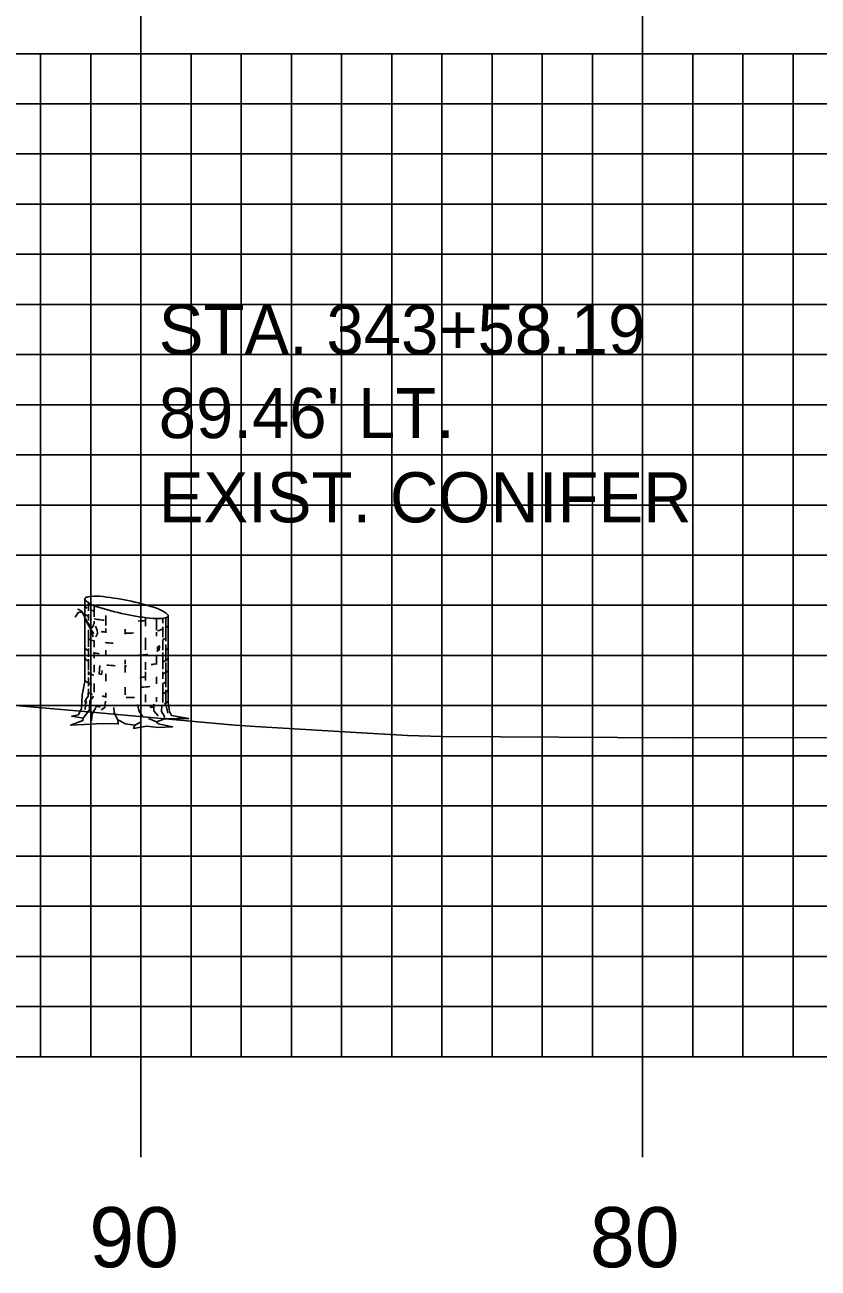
# Model space of a CAD drawing. Extents: x 1825147 to 1825490, y 442591 to 442811.
# Drawn here: x 1825220.05 to 1825235.86, y 442764.45 to 442789.24 of the extents above; entities that cross this region are included whole.
import ezdxf

# ---------------------------------------------------------------- set-up
doc = ezdxf.new("R2010")
doc.units = 0
for name, color, linetype in [('D_Text_Monospaced', 7, 'Continuous'), ('H_V ANNOTATION', 7, 'Continuous'), ('M_Trees_Conifer_Pay', 7, 'Continuous'), ('MAJOR', 7, 'Continuous'), ('MINOR', 7, 'Continuous'), ('S_Roadway_Centerline', 7, 'Continuous')]:
    doc.layers.add(name, color=color, linetype=linetype)

msp = doc.modelspace()

# ---------------------------------------------------------------- linework, layer by layer
at = {"layer": 'M_Trees_Conifer_Pay'}
for p, q in [((1825221.242, 442776.145), (1825221.242, 442777.792)), ((1825221.313, 442777.719), (1825221.313, 442777.557)), ((1825221.313, 442777.489), (1825221.313, 442777.361)), ((1825221.431, 442777.658), (1825221.431, 442777.435)), ((1825221.431, 442777.347), (1825221.431, 442777.299)), ((1825221.659, 442777.462), (1825221.659, 442777.263)), ((1825222.455, 442777.42), (1825222.455, 442777.252)), ((1825222.675, 442777.4), (1825222.675, 442777.168)), ((1825222.8, 442777.408), (1825222.8, 442777.31)), ((1825222.8, 442777.236), (1825222.8, 442777.032)), ((1825222.859, 442777.419), (1825222.859, 442776.948)), ((1825222.906, 442775.734), (1825222.906, 442777.456)), ((1825221.313, 442777.174), (1825221.313, 442776.838)), ((1825221.374, 442777.164), (1825221.425, 442777.104)), ((1825221.659, 442777.205), (1825221.659, 442777.116)), ((1825222.05, 442777.189), (1825222.05, 442777.093)), ((1825222.455, 442777.015), (1825222.455, 442776.778)), ((1825222.675, 442777.127), (1825222.675, 442777.053)), ((1825221.313, 442776.801), (1825221.313, 442776.639)), ((1825221.431, 442776.964), (1825221.431, 442776.832)), ((1825221.659, 442776.769), (1825221.659, 442776.664)), ((1825222.8, 442776.974), (1825222.8, 442776.774)), ((1825222.859, 442776.883), (1825222.859, 442776.575)), ((1825221.313, 442776.591), (1825221.313, 442776.375)), ((1825221.431, 442776.721), (1825221.431, 442776.612)), ((1825222.05, 442776.575), (1825222.05, 442776.501)), ((1825222.455, 442776.534), (1825222.455, 442776.381)), ((1825222.675, 442776.649), (1825222.675, 442776.511)), ((1825222.8, 442776.727), (1825222.8, 442776.391)), ((1825222.859, 442776.528), (1825222.859, 442776.036)), ((1825221.313, 442776.344), (1825221.313, 442776.27)), ((1825221.431, 442776.476), (1825221.431, 442776.334)), ((1825221.659, 442776.297), (1825221.659, 442776.15)), ((1825222.05, 442776.476), (1825222.05, 442776.328)), ((1825222.455, 442776.338), (1825222.455, 442776.165)), ((1825222.675, 442776.239), (1825222.675, 442776.097)), ((1825222.8, 442776.338), (1825222.8, 442776.202)), ((1825221.313, 442776.229), (1825221.313, 442776.056)), ((1825221.431, 442776.107), (1825221.431, 442775.935)), ((1825222.05, 442776.036), (1825222.05, 442775.883)), ((1825222.8, 442776.103), (1825222.8, 442775.725)), ((1825221.659, 442775.918), (1825221.659, 442775.83)), ((1825222.455, 442775.887), (1825222.455, 442775.734)), ((1825222.675, 442775.835), (1825222.675, 442775.741)), ((1825222.859, 442775.982), (1825222.859, 442775.734)), ((1825222.238, 442775.277), (1825222.364, 442775.341)), ((1825222.675, 442775.341), (1825222.512, 442775.405))]:
    msp.add_line(p, q, dxfattribs=at)
for points in [[(1825221.196, 442777.522), (1825221.12, 442777.53), (1825221.048, 442777.431)], [(1825221.425, 442777.29), (1825221.388, 442777.215), (1825221.341, 442777.272), (1825221.283, 442777.341), (1825221.191, 442777.534), (1825221.126, 442777.582), (1825221.095, 442777.588)], [(1825221.41, 442777.036), (1825221.374, 442777.164), (1825221.31, 442777.279), (1825221.279, 442777.347), (1825221.21, 442777.493)], [(1825221.458, 442777.252), (1825221.489, 442777.168), (1825221.493, 442777.1), (1825221.462, 442777.036)], [(1825222.727, 442776.762), (1825222.733, 442776.857), (1825222.689, 442776.834), (1825222.689, 442776.74)], [(1825221.588, 442776.363), (1825221.575, 442776.286), (1825221.528, 442776.297), (1825221.54, 442776.463)], [(1825221.242, 442776.145), (1825221.191, 442775.883), (1825221.174, 442775.609), (1825221.116, 442775.484), (1825220.981, 442775.453), (1825221.211, 442775.416), (1825221.211, 442775.416), (1825221.205, 442775.368), (1825220.958, 442775.274), (1825221.232, 442775.29), (1825221.588, 442775.311), (1825221.909, 442775.3), (1825221.903, 442775.383), (1825222.051, 442775.3), (1825222.238, 442775.277), (1825222.214, 442775.21), (1825222.481, 442775.253), (1825222.702, 442775.226), (1825222.994, 442775.243), (1825222.706, 442775.3), (1825222.675, 442775.341), (1825222.838, 442775.399), (1825223.074, 442775.41), (1825223.315, 442775.41), (1825222.973, 442775.467), (1825222.932, 442775.547), (1825222.906, 442775.734)], [(1825221.316, 442776.002), (1825221.31, 442775.856), (1825221.263, 442775.788), (1825221.252, 442775.589)], [(1825221.415, 442775.856), (1825221.341, 442775.751), (1825221.336, 442775.578), (1825221.211, 442775.416)], [(1825221.652, 442775.751), (1825221.641, 442775.626), (1825221.567, 442775.582)], [(1825221.374, 442775.362), (1825221.388, 442775.5), (1825221.462, 442775.629)], [(1825221.903, 442775.383), (1825221.828, 442775.524), (1825221.819, 442775.626)], [(1825222.391, 442775.453), (1825222.323, 442775.547), (1825222.296, 442775.687)], [(1825222.617, 442775.694), (1825222.617, 442775.562), (1825222.706, 442775.463)], [(1825222.78, 442775.667), (1825222.774, 442775.551), (1825222.827, 442775.463), (1825222.838, 442775.399)], [(1825222.858, 442775.687), (1825222.879, 442775.609), (1825222.899, 442775.515)]]:
    msp.add_lwpolyline(points, dxfattribs=at)
for centre, radius, start, end in [((1825221.264, 442777.792), 0.0226, 156.5926, 168.2806), ((1825221.264, 442777.792), 0.0226, 168.2806, 179.9685), ((1825221.268, 442777.792), 0.0264, 179.9685, 190.7806), ((1825221.273, 442777.793), 0.0314, 190.7806, 203.4842), ((1825221.268, 442777.79), 0.0264, 145.7806, 156.5926), ((1825221.293, 442777.801), 0.0527, 203.4842, 213.2806), ((1825221.272, 442777.787), 0.0314, 133.077, 145.7806), ((1825221.317, 442777.817), 0.0817, 213.2806, 227.6113), ((1825221.286, 442777.772), 0.0527, 123.2806, 133.077), ((1825221.302, 442777.748), 0.0817, 108.9499, 123.2806), ((1825221.431, 442777.942), 0.251, 227.6113, 235.7806), ((1825221.357, 442777.588), 0.251, 100.7806, 108.9499), ((1825221.741, 442778.397), 0.802, 235.7806, 251.9406), ((1825221.46, 442777.047), 0.802, 84.6206, 100.7806), ((1825221.05, 442772.689), 5.179, 78.2806, 84.6206), ((1825221.05, 442772.689), 5.179, 71.9406, 78.2806), ((1825221.275, 442777.665), 0.0334, 185.7849, 196.0515), ((1825221.275, 442777.511), 0.0334, 185.7849, 196.0515), ((1825221.285, 442777.668), 0.0441, 196.0515, 210), ((1825221.285, 442777.514), 0.0441, 196.0515, 210), ((1825221.301, 442777.677), 0.0624, 210, 228.7494), ((1825221.301, 442777.523), 0.0624, 210, 228.7494), ((1825221.373, 442777.76), 0.172, 228.7494, 240), ((1825221.373, 442777.606), 0.172, 228.7494, 240), ((1825221.573, 442778.105), 0.571, 247.5868, 255.5683), ((1825223.097, 442782.559), 5.179, 251.9406, 258.2806), ((1825223.097, 442782.559), 5.179, 258.2806, 264.6206), ((1825222.407, 442776.85), 0.802, 55.7806, 71.9406), ((1825222.717, 442777.306), 0.251, 47.6113, 55.7806), ((1825222.831, 442777.431), 0.0817, 33.2806, 47.6113), ((1825222.855, 442777.447), 0.0527, 23.4842, 33.2806), ((1825221.573, 442777.951), 0.571, 240, 242.9763), ((1825221.573, 442777.951), 0.571, 255.6333, 261.8968), ((1825222.074, 442781.468), 4.124, 261.8968, 263.762), ((1825222.074, 442781.468), 4.124, 273.2669, 275.3045), ((1825222.687, 442778.201), 0.802, 264.6206, 280.7806), ((1825222.79, 442777.66), 0.251, 280.7806, 288.9499), ((1825222.576, 442777.718), 0.571, 299.6633, 300), ((1825222.775, 442777.373), 0.172, 300, 311.2506), ((1825222.845, 442777.5), 0.0817, 288.9499, 303.2806), ((1825222.847, 442777.29), 0.0624, 311.2506, 330), ((1825222.861, 442777.476), 0.0527, 303.2806, 313.077), ((1825222.875, 442777.46), 0.0314, 313.077, 325.7806), ((1825222.88, 442777.457), 0.0264, 325.7806, 336.5926), ((1825222.863, 442777.281), 0.0441, 330, 343.9485), ((1825222.874, 442777.455), 0.0314, 10.7806, 23.4842), ((1825222.883, 442777.456), 0.0226, 336.5926, 348.2806), ((1825222.879, 442777.456), 0.0264, 359.9685, 10.7806), ((1825222.883, 442777.456), 0.0226, 348.2806, 359.9685), ((1825222.874, 442777.278), 0.0334, 0, 16.0515), ((1825222.874, 442777.278), 0.0334, 343.9485, 360), ((1825221.275, 442777.067), 0.0334, 185.7849, 196.0515), ((1825221.573, 442777.507), 0.571, 242.9571, 255.5507), ((1825222.075, 442781.235), 4.124, 262.9442, 264.2151), ((1825222.075, 442781.235), 4.124, 269.6419, 270), ((1825222.075, 442781.235), 4.124, 270, 271.9249), ((1825222.576, 442777.718), 0.571, 282.0154, 293.1403), ((1825222.575, 442777.507), 0.571, 292.9413, 300), ((1825221.276, 442776.831), 0.0334, 185.7849, 196.0515), ((1825221.287, 442776.834), 0.0441, 196.0515, 210), ((1825221.302, 442776.843), 0.0624, 210, 228.7494), ((1825221.375, 442776.926), 0.172, 228.7494, 240), ((1825221.574, 442777.271), 0.571, 240, 242.8104), ((1825222.074, 442781.024), 4.124, 264.0496, 266.2948), ((1825222.576, 442777.271), 0.571, 299.6633, 300), ((1825222.775, 442776.926), 0.172, 300, 311.2506), ((1825222.847, 442776.843), 0.0624, 311.2506, 330), ((1825222.863, 442776.834), 0.0441, 330, 343.9485), ((1825222.874, 442776.831), 0.0334, 0, 16.0515), ((1825222.874, 442776.831), 0.0334, 343.9485, 360), ((1825221.276, 442776.621), 0.0334, 185.7849, 196.0515), ((1825221.287, 442776.624), 0.0441, 196.0515, 210), ((1825221.302, 442776.633), 0.0624, 210, 228.7494), ((1825221.375, 442776.716), 0.172, 228.7494, 240), ((1825221.574, 442777.061), 0.571, 240, 242.8104), ((1825221.574, 442777.271), 0.571, 253.0704, 261.8968), ((1825222.075, 442780.788), 4.124, 261.8968, 262.3875), ((1825222.075, 442780.788), 4.124, 273.3324, 275.919), ((1825222.075, 442780.578), 4.124, 276.8526, 278.1032), ((1825222.576, 442777.061), 0.571, 278.1032, 280.7293), ((1825222.576, 442777.061), 0.571, 293.1403, 300), ((1825222.775, 442776.716), 0.172, 300, 311.2506), ((1825222.847, 442776.633), 0.0624, 311.2506, 330), ((1825222.863, 442776.624), 0.0441, 330, 343.9485), ((1825222.874, 442776.621), 0.0334, 0, 16.0515), ((1825222.874, 442776.621), 0.0334, 343.9485, 360), ((1825221.574, 442776.824), 0.571, 242.8104, 254.6017), ((1825222.075, 442780.578), 4.124, 264.5431, 266.8507), ((1825222.075, 442780.578), 4.124, 269.6419, 270), ((1825222.075, 442780.342), 4.124, 273.6807, 275.284), ((1825222.576, 442776.824), 0.571, 293.1403, 300), ((1825222.775, 442776.479), 0.172, 300, 311.2506), ((1825222.847, 442776.396), 0.0624, 311.2506, 330), ((1825222.863, 442776.387), 0.0441, 330, 343.9485), ((1825222.874, 442776.384), 0.0334, 0, 16.0515), ((1825222.874, 442776.384), 0.0334, 343.9485, 360), ((1825221.276, 442776.187), 0.0334, 185.7849, 196.0515), ((1825221.287, 442776.19), 0.0441, 196.0515, 210), ((1825221.302, 442776.199), 0.0624, 210, 228.7494), ((1825221.375, 442776.281), 0.172, 228.7494, 240), ((1825221.574, 442776.626), 0.571, 240, 250.7093), ((1825222.075, 442780.144), 4.124, 274.1603, 276.5009), ((1825222.587, 442776.633), 0.571, 291.9732, 298.7631), ((1825222.874, 442776.187), 0.0334, 0, 16.0515), ((1825222.874, 442775.991), 0.0334, 0, 16.0515), ((1825222.874, 442775.991), 0.0334, 343.9485, 360), ((1825221.276, 442775.771), 0.0334, 185.7849, 196.0515), ((1825221.287, 442775.774), 0.0441, 196.0515, 210), ((1825221.302, 442775.783), 0.0624, 210, 228.7494), ((1825221.375, 442775.866), 0.172, 228.7494, 240), ((1825221.574, 442776.431), 0.571, 242.7279, 251.4933), ((1825222.075, 442779.948), 4.124, 263.2104, 264.2151), ((1825222.075, 442779.948), 4.124, 269.8672, 270), ((1825222.075, 442779.948), 4.124, 270, 272.1883), ((1825222.576, 442776.431), 0.571, 293.1403, 300), ((1825222.775, 442776.086), 0.172, 300, 311.2506), ((1825222.775, 442775.866), 0.172, 300, 311.2506), ((1825222.847, 442776.003), 0.0624, 311.2506, 330), ((1825222.847, 442775.783), 0.0624, 311.2506, 330), ((1825222.863, 442775.994), 0.0441, 330, 343.9485), ((1825222.863, 442775.774), 0.0441, 330, 343.9485), ((1825222.874, 442775.771), 0.0334, 0, 16.0515), ((1825222.874, 442775.771), 0.0334, 343.9485, 360), ((1825221.574, 442776.211), 0.571, 258.363, 261.8968), ((1825222.075, 442779.728), 4.124, 261.8968, 262.6316), ((1825222.075, 442779.728), 4.124, 276.488, 277.5562), ((1825222.576, 442776.211), 0.571, 295.4686, 300)]:
    msp.add_arc(centre, radius, start, end, dxfattribs=at)
at = {"layer": 'MAJOR'}
for p, q in [((1825222.361, 442790.669), (1825222.361, 442788.665)), ((1825232.361, 442790.669), (1825232.361, 442788.665)), ((1825172.361, 442788.665), (1825452.361, 442788.665)), ((1825172.361, 442788.665), (1825452.361, 442788.665)), ((1825222.361, 442768.665), (1825222.361, 442788.665)), ((1825232.361, 442768.665), (1825232.361, 442788.665)), ((1825172.361, 442783.665), (1825452.361, 442783.665)), ((1825172.361, 442778.665), (1825452.361, 442778.665)), ((1825172.361, 442773.665), (1825452.361, 442773.665)), ((1825172.361, 442768.665), (1825452.361, 442768.665)), ((1825172.361, 442768.665), (1825452.361, 442768.665)), ((1825222.361, 442766.661), (1825222.361, 442768.665)), ((1825232.361, 442766.661), (1825232.361, 442768.665))]:
    msp.add_line(p, q, dxfattribs=at)
at = {"layer": 'MINOR'}
for p, q in [((1825220.361, 442768.665), (1825220.361, 442788.665)), ((1825221.361, 442768.665), (1825221.361, 442788.665)), ((1825223.361, 442768.665), (1825223.361, 442788.665)), ((1825224.361, 442768.665), (1825224.361, 442788.665)), ((1825225.361, 442768.665), (1825225.361, 442788.665)), ((1825226.361, 442768.665), (1825226.361, 442788.665)), ((1825227.361, 442768.665), (1825227.361, 442788.665)), ((1825228.361, 442768.665), (1825228.361, 442788.665)), ((1825229.361, 442768.665), (1825229.361, 442788.665)), ((1825230.361, 442768.665), (1825230.361, 442788.665)), ((1825231.361, 442768.665), (1825231.361, 442788.665)), ((1825233.361, 442768.665), (1825233.361, 442788.665)), ((1825234.361, 442768.665), (1825234.361, 442788.665)), ((1825235.361, 442768.665), (1825235.361, 442788.665)), ((1825172.361, 442787.665), (1825452.361, 442787.665)), ((1825172.361, 442786.665), (1825452.361, 442786.665)), ((1825172.361, 442785.665), (1825452.361, 442785.665)), ((1825172.361, 442784.665), (1825452.361, 442784.665)), ((1825172.361, 442782.665), (1825452.361, 442782.665)), ((1825172.361, 442781.665), (1825452.361, 442781.665)), ((1825172.361, 442780.665), (1825452.361, 442780.665)), ((1825172.361, 442779.665), (1825452.361, 442779.665)), ((1825172.361, 442777.665), (1825452.361, 442777.665)), ((1825172.361, 442776.665), (1825452.361, 442776.665)), ((1825172.361, 442775.665), (1825452.361, 442775.665)), ((1825172.361, 442774.665), (1825452.361, 442774.665)), ((1825172.361, 442772.665), (1825452.361, 442772.665)), ((1825172.361, 442771.665), (1825452.361, 442771.665)), ((1825172.361, 442770.665), (1825452.361, 442770.665)), ((1825172.361, 442769.665), (1825452.361, 442769.665))]:
    msp.add_line(p, q, dxfattribs=at)
at = {"layer": 'S_Roadway_Centerline'}
msp.add_lwpolyline([(1825200.366, 442776.551), (1825204.657, 442776.532), (1825206.293, 442776.503), (1825209.222, 442776.516), (1825210.383, 442776.517), (1825211.047, 442776.362), (1825215.483, 442776.048), (1825221.234, 442775.545), (1825224.236, 442775.276), (1825224.639, 442775.252), (1825226.531, 442775.134), (1825227.676, 442775.072), (1825228.368, 442775.05), (1825233.027, 442775.026), (1825236.221, 442775.027), (1825236.992, 442775.01), (1825240.062, 442774.843), (1825242.28, 442774.783), (1825243.751, 442774.801), (1825250.644, 442775.072), (1825260.365, 442775.484), (1825261.114, 442775.451), (1825271.443, 442775.535)], dxfattribs=at)

# ---------------------------------------------------------------- texts
at = {"layer": 'D_Text_Monospaced'}
for s, height, p in [('STA. 343+58.19', 0.99996, (1825222.716, 442782.667)), ("89.46' LT.", 1, (1825222.716, 442780.999)), ('EXIST. CONIFER', 0.99996, (1825222.716, 442779.319))]:
    msp.add_text(s, height=height, dxfattribs=at).set_placement(p)
at = {"layer": 'H_V ANNOTATION'}
for s, p in [('90', (1825221.333, 442764.465)), ('80', (1825231.312, 442764.465))]:
    msp.add_text(s, height=1.2, dxfattribs=at).set_placement(p)

doc.saveas('drawing.dxf')
